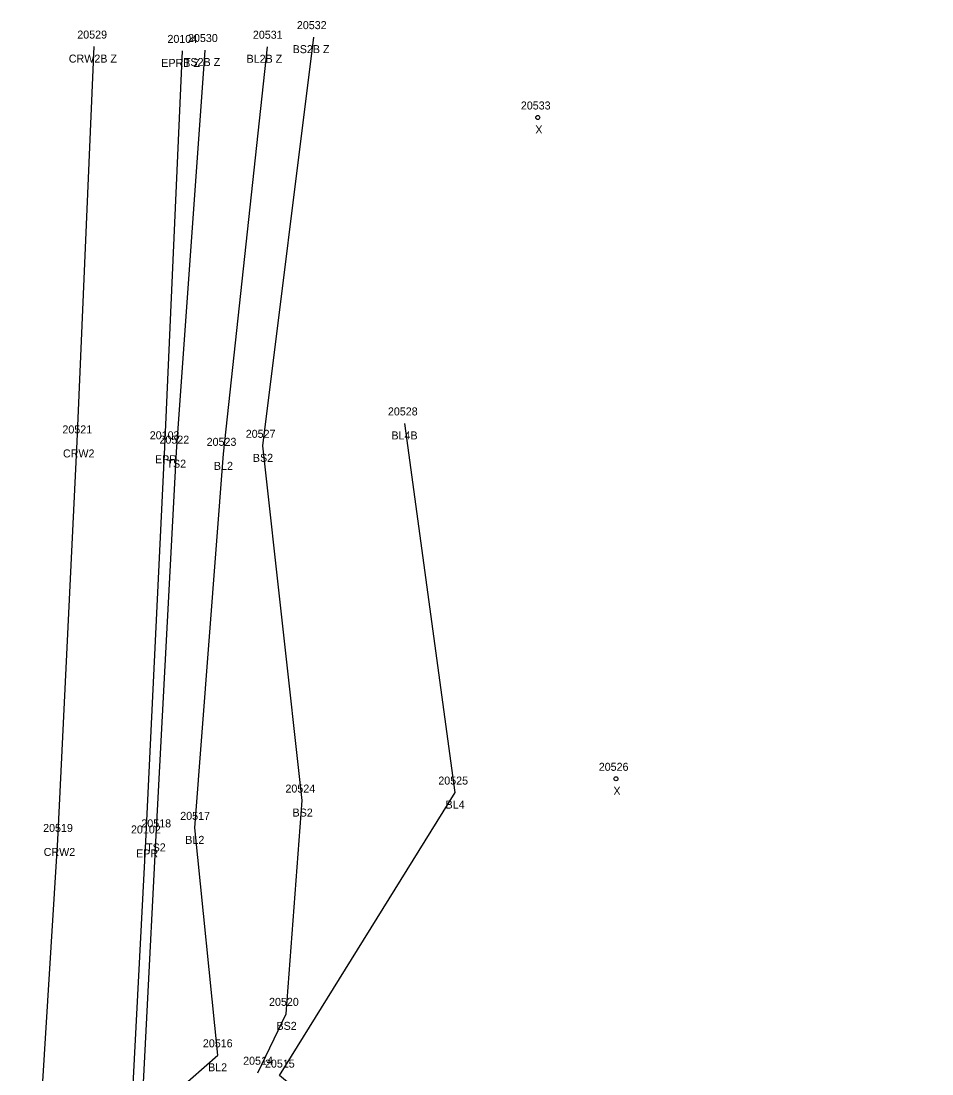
# Model space of a CAD drawing. Extents: x 1813127 to 1814107, y 1178171 to 1179078.
# Drawn here: x 1813671.6 to 1813785.5, y 1178917.6 to 1179049.2 of the extents above; entities that cross this region are included whole.
import ezdxf

# ---------------------------------------------------------------- set-up
doc = ezdxf.new("R2010")
doc.units = 0
for name, color, linetype in [('RD_DTM_BkLn1', 7, 'Continuous'), ('RD_DTM_BkLn2', 7, 'Continuous'), ('RD_EX_Road', 7, 'Continuous'), ('RD_EX_Road_txCode', 7, 'Continuous'), ('RD_SMD_Locator', 7, 'Continuous'), ('RD_SMD_Misc', 7, 'Continuous')]:
    doc.layers.add(name, color=color, linetype=linetype)

msp = doc.modelspace()

# ---------------------------------------------------------------- linework, layer by layer
at = {"layer": 'RD_DTM_BkLn1'}
for points in [[(1813652.18, 1178753.85), (1813654.73, 1178764.67), (1813662.67, 1178799.96), (1813669.51, 1178850.38), (1813669.19, 1178849.87), (1813673.32, 1178899.93), (1813676.21, 1178946.85), (1813678.62, 1178996.65), (1813680.77, 1179045.99)], [(1813781.56, 1178808.06), (1813739.7, 1178830.55), (1813722.3, 1178851.85), (1813723.99, 1178876.11), (1813711.97, 1178887.08), (1813691.11, 1178915.45), (1813696.21, 1178919.94), (1813693.36, 1178948.36), (1813696.93, 1178995.1), (1813702.43, 1179045.97)], [(1813785.49, 1178821.63), (1813744.83, 1178844.78), (1813733.94, 1178853.89), (1813739.08, 1178880.23), (1813725.13, 1178902.21), (1813713.29, 1178909.62), (1813703.94, 1178917.4), (1813725.9, 1178952.77), (1813719.6, 1178998.9)]]:
    msp.add_lwpolyline(points, dxfattribs=at)
at = {"layer": 'RD_DTM_BkLn2'}
for points in [[(1813701.21, 1178917.76), (1813704.78, 1178925.12), (1813706.78, 1178951.77), (1813701.83, 1178996.1), (1813708.22, 1179047.17)], [(1813751.85, 1178730.74), (1813741.17, 1178742.44), (1813717.67, 1178762.1), (1813698.84, 1178775.48), (1813689.15, 1178782.4), (1813688.55, 1178790.23), (1813686.56, 1178796.15), (1813687.57, 1178849.05), (1813684.25, 1178850.31), (1813686.08, 1178900.25), (1813688.49, 1178947.42), (1813691.04, 1178995.37), (1813694.64, 1179045.56)]]:
    msp.add_lwpolyline(points, dxfattribs=at)
at = {"layer": 'RD_EX_Road'}
msp.add_lwpolyline([(1813750.48, 1178727.17), (1813739.94, 1178735.23), (1813706.04, 1178760.25), (1813693.68, 1178773.78), (1813687.15, 1178785.68), (1813683.91, 1178796.53), (1813681.81, 1178824.01), (1813682.76, 1178849.48), (1813684.82, 1178900.28), (1813687.23, 1178946.66), (1813689.58, 1178995.92), (1813691.79, 1179045.45)], dxfattribs=at)
at = {"layer": 'RD_SMD_Locator'}
for centre, radius in [((1813708.22, 1179047.17), 0.001), ((1813680.77, 1179045.99), 0.001), ((1813691.79, 1179045.45), 0.001), ((1813694.64, 1179045.56), 0.001), ((1813702.43, 1179045.97), 0.001), ((1813736.22, 1179037.13), 0.25), ((1813719.6, 1178998.9), 0.001), ((1813678.62, 1178996.65), 0.001), ((1813689.58, 1178995.92), 0.001), ((1813691.04, 1178995.37), 0.001), ((1813701.83, 1178996.1), 0.001), ((1813696.93, 1178995.1), 0.001), ((1813745.99, 1178954.49), 0.25), ((1813725.9, 1178952.77), 0.001), ((1813706.78, 1178951.77), 0.001), ((1813693.36, 1178948.36), 0.001), ((1813676.21, 1178946.85), 0.001), ((1813687.23, 1178946.66), 0.001), ((1813688.49, 1178947.42), 0.001), ((1813704.78, 1178925.12), 0.001), ((1813696.21, 1178919.94), 0.001), ((1813701.21, 1178917.76), 0.001)]:
    msp.add_circle(centre, radius, dxfattribs=at)

# ---------------------------------------------------------------- texts
at = {"layer": 'RD_EX_Road_txCode'}
for s, p in [('20104', (1813689.92, 1179046.45)), ('EPRB Z', (1813689.15, 1179043.45)), ('20103', (1813687.71, 1178996.92)), ('EPR', (1813688.36, 1178993.92)), ('20102', (1813685.36, 1178947.66)), ('EPR', (1813686, 1178944.66))]:
    msp.add_text(s, height=1, dxfattribs=at).set_placement(p)
at = {"layer": 'RD_SMD_Misc'}
for s, p in [('20532', (1813706.1, 1179048.17)), ('20529', (1813678.65, 1179046.99)), ('20531', (1813700.6, 1179046.97)), ('20530', (1813692.49, 1179046.56)), ('BS2B Z', (1813705.57, 1179045.17)), ('CRW2B Z', (1813677.59, 1179043.99)), ('TS2B Z', (1813691.98, 1179043.56)), ('BL2B Z', (1813699.81, 1179043.97)), ('20533', (1813734.1, 1179038.13)), ('X', (1813735.91, 1179035.13)), ('20528', (1813717.48, 1178999.9)), ('20521', (1813676.79, 1178997.65)), ('20527', (1813699.71, 1178997.1)), ('BL4B', (1813717.92, 1178996.9)), ('20522', (1813688.92, 1178996.37)), ('20523', (1813694.82, 1178996.1)), ('CRW2', (1813676.86, 1178994.65)), ('TS2', (1813689.8, 1178993.37)), ('BL2', (1813695.73, 1178993.1)), ('BS2', (1813700.6, 1178994.1)), ('20526', (1813743.84, 1178955.49)), ('20525', (1813723.78, 1178953.77)), ('20524', (1813704.67, 1178952.77)), ('X', (1813745.67, 1178952.49)), ('BS2', (1813705.56, 1178949.77)), ('BL4', (1813724.69, 1178950.77)), ('20518', (1813686.66, 1178948.42)), ('20517', (1813691.52, 1178949.36)), ('20519', (1813674.38, 1178947.85)), ('BL2', (1813692.15, 1178946.36)), ('CRW2', (1813674.45, 1178944.85)), ('TS2', (1813687.25, 1178945.42)), ('20520', (1813702.62, 1178926.12)), ('BS2', (1813703.55, 1178923.12)), ('20516', (1813694.35, 1178920.94)), ('BL2', (1813695, 1178917.94)), ('20514', (1813699.38, 1178918.76)), ('20515', (1813702.11, 1178918.4))]:
    msp.add_text(s, height=1, dxfattribs=at).set_placement(p)

doc.saveas('drawing.dxf')
